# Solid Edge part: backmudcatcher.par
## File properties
Author: morva
Template: iso metric part.par
Last saved by: morva
Revision: 23
Application: Solid Edge
Density: 1385.000 kg/m^3
Accuracy: 0.990
Username: morva
Material: PVC
Face Style: Tan
Fill Style: ANSI34(Plastic)
Virtual Style: ANSI34(Plastic)
Grouping: Non-metals\Plastics
LibraryName: Materials
Coef. of Thermal Exp: 9e-05
Thermal Conductivity: 1.5
Specific Heat: 0.0
Modulus of Elasticity: 2757903000.0
Poisson's Ratio: 0.4
Yield Stress: 6894757.0
Ultimate Stress: 0.0
Elongation: 0.0
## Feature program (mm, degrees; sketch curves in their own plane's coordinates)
sketch for "unnamed RevolvedProtrusion 1" plane through (0, 0, 0) normal (0, 0, 1) x-axis (1, 0, 0)
  line (-41, 118.5472) -> (-41, 132.791)
  line (41, 118.5472) -> (41, 132.791)
revolve "unnamed RevolvedProtrusion 1" add finite
sketch for "ExtrudedProtrusion_2" plane through (0, -110.6061, 29.6368) normal (0, -0.965926, 0.258819) x-axis (-1, 0, 0)
extrude "ExtrudedProtrusion_2" add finite 100 along +normal
sketch for "unnamed RevolvedCutout 1" plane through (0, 0, 0) normal (0, 0, 1) x-axis (1, 0, 0)
revolve "unnamed RevolvedCutout 1" cut finite 360 deg
sketch for "ExtrudedCutout_2" plane through (0, -152.5691, 66.2139) normal (0, -0.258819, -0.965926) x-axis (0, -0.965926, 0.258819)
extrude "ExtrudedCutout_2" cut finite 2 along -normal
sketch for "Hole_1" plane through (0, -152.8296, 81.8128) normal (0, 0.258819, 0.965926) x-axis (1, 0, 0)
hole "Hole_1" diameter 8 through  CounterSinkAngle = 90 deg; Head_Clearance = 0.4 mm
sketch for "unnamed Hole 1" plane through (0, -152.8296, 81.8128) normal (0, 0.258819, 0.965926) x-axis (1, 0, 0)
hole "unnamed Hole 1" through
pattern "unnamed Pattern 1" of "Hole_1", "unnamed Hole 1"
chamfer "Chamfer_6" setback 5
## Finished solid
Body 1: solid body, 17 faces, 33 edges, 16 vertices.
  Faces by surface: plane 9, cylinder 4, cone 2, torus 2
  Edges by curve: line 15, circle 14, intersection 4
Bounding box of the edges (mm; curved faces can reach further): 82.000 x 352.848 x 132.791, from (-41, -200.3477, 0) to (41, 152.5, 132.791).
Cylindrical faces by radius (mm): R4 x2, R8 x2
Conical faces (half-angle, radius in mm at the cone's reference point): 45 deg R8 x2
Toroidal faces (ring radius, tube radius in mm): R100 r45 x1, R100 r52.5 x1
Planar faces by outward normal: +x 1, -x 1, -z 1, oblique 6
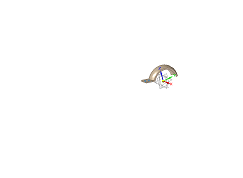
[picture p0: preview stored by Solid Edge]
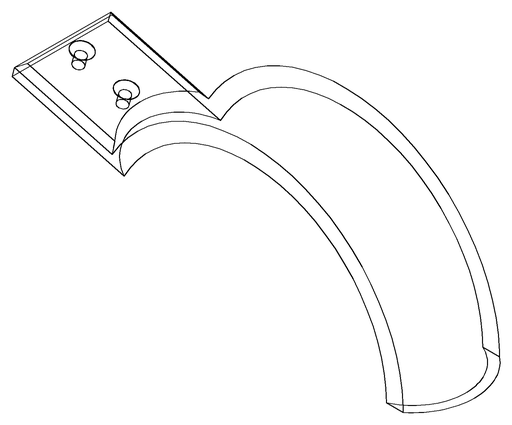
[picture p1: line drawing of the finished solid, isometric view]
